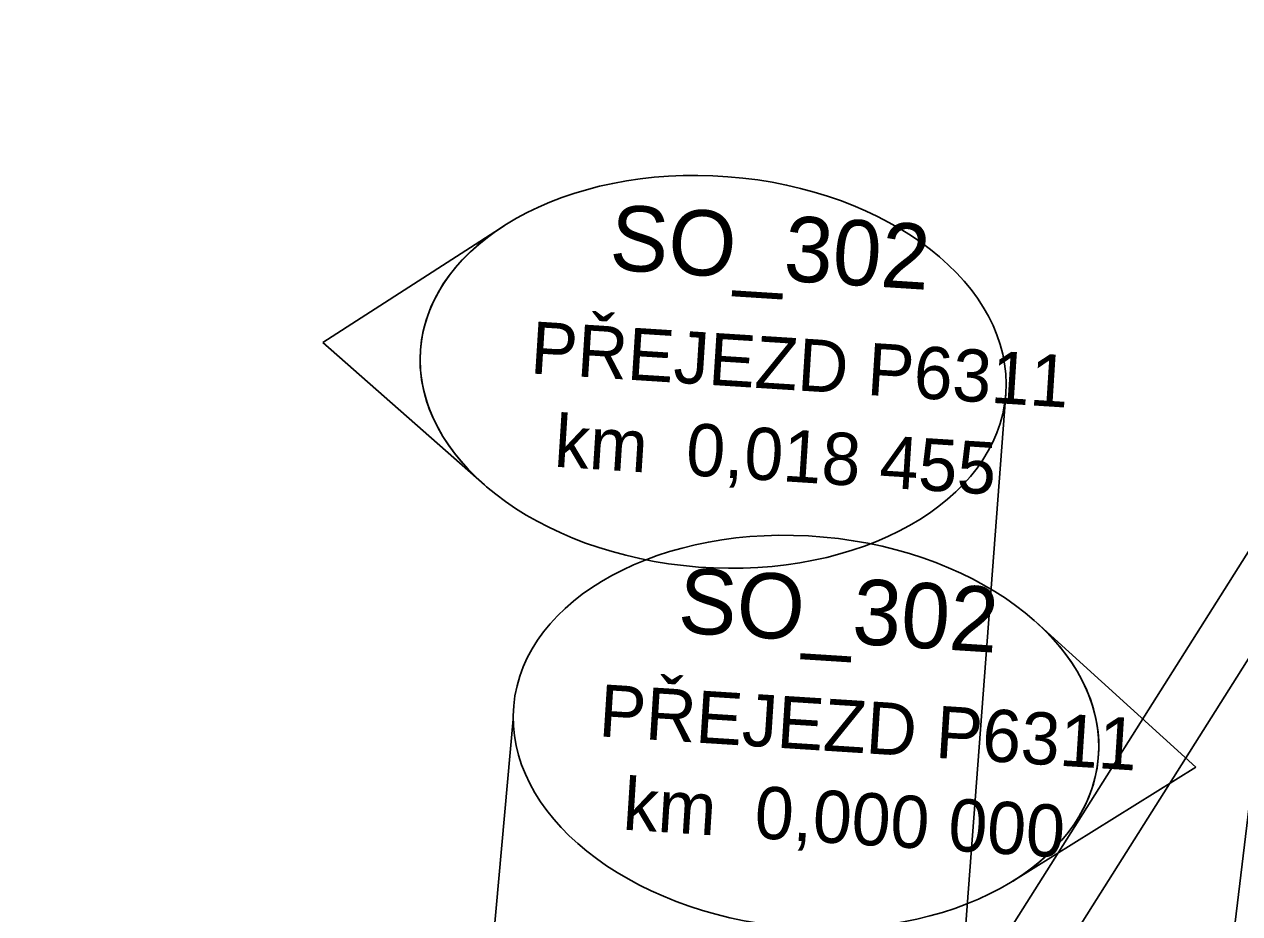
# Model space of a CAD drawing. Extents: x -743359 to -742769, y -1127804 to -1126284.
# Drawn here: x -743198.3 to -743151.71, y -1127071.55 to -1127037.47 of the extents above; entities that cross this region are included whole.
import ezdxf

# ---------------------------------------------------------------- set-up
doc = ezdxf.new("R2010")
doc.units = 0
for name, color, linetype in [('_Násyp', 7, 'Continuous'), ('_Zabezpečovací zařízení_trasa', 7, 'Continuous'), ('bublina_fialová_čára_tenká', 7, 'Continuous'), ('bublina_růžová_230_čára_tučná', 7, 'Continuous'), ('SMER_VYS_VYROVNANI', 7, 'Continuous')]:
    doc.layers.add(name, color=color, linetype=linetype)

msp = doc.modelspace()

# ---------------------------------------------------------------- linework, layer by layer
at = {"layer": '_Zabezpečovací zařízení_trasa'}
msp.add_lwpolyline([(-743098.647, -1126974.146), (-743125.94, -1127017.384), (-743152.604, -1127059.608), (-743175.023, -1127095.116), (-743199.163, -1127133.346), (-743215.971, -1127159.941), (-743232.818, -1127186.515), (-743247.456, -1127209.811), (-743254.52, -1127221.639), (-743261.299, -1127233.691), (-743264.155, -1127239.195), (-743264.862, -1127241.108), (-743267.337, -1127245.816), (-743268.289, -1127247.159), (-743271.711, -1127253.75), (-743281.122, -1127274.196), (-743291.923, -1127301.42), (-743296.724, -1127315.222), (-743301.116, -1127329.128), (-743306.787, -1127349.506), (-743311.536, -1127370.056), (-743315.693, -1127392.87), (-743318.79, -1127415.837)], dxfattribs=at)
at = {"layer": 'bublina_fialová_čára_tenká'}
for p, q in [((-743145.088, -1127015.481), (-743152.928, -1127080.479)), ((-743160.679, -1127051.634), (-743164.286, -1127099.423)), ((-743179.562, -1127064.096), (-743182.5, -1127096.45))]:
    msp.add_line(p, q, dxfattribs=at)
at = {"layer": 'bublina_růžová_230_čára_tučná'}
for p, q in [((-743179.913, -1127045.19), (-743186.854, -1127049.658)), ((-743179.913, -1127045.19), (-743186.854, -1127049.658)), ((-743186.854, -1127049.658), (-743180.663, -1127055.117)), ((-743186.854, -1127049.658), (-743180.663, -1127055.117)), ((-743159.51, -1127060.384), (-743153.397, -1127065.932)), ((-743159.51, -1127060.384), (-743153.397, -1127065.932)), ((-743153.397, -1127065.932), (-743160.402, -1127070.299)), ((-743153.397, -1127065.932), (-743160.402, -1127070.299))]:
    msp.add_line(p, q, dxfattribs=at)
for centre, major_axis in [((-743171.897, -1127050.787), (11.218, -0.847)), ((-743168.337, -1127064.588), (-11.205, 1.008))]:
    msp.add_ellipse(centre, major_axis=major_axis, ratio=0.666667, dxfattribs=at)
for centre, major_axis in [((-743171.897, -1127050.787), (-11.22, 0.847)), ((-743168.337, -1127064.588), (11.206, -1.008))]:
    msp.add_ellipse(centre, major_axis=major_axis, ratio=0.666473, start_param=5.557317, end_param=7.009053, dxfattribs=at)
at = {"layer": 'SMER_VYS_VYROVNANI'}
msp.add_lwpolyline([(-743143.427, -1127049.192), (-743169.53, -1127090.542)], dxfattribs=at)

# ---------------------------------------------------------------- texts
at = {"layer": '_Násyp'}
for s, height, p in [('SO_302', 2.5, (-743175.908, -1127046.867)), ('PŘEJEZD P6311', 2, (-743178.937, -1127050.846)), ('km  0,018 455', 2, (-743178.022, -1127054.419)), ('SO_302', 2.5, (-743173.286, -1127060.774)), ('PŘEJEZD P6311', 2, (-743176.314, -1127064.752)), ('km  0,000 000', 2, (-743175.393, -1127068.327))]:
    msp.add_text(s, height=height, rotation=356.3528, dxfattribs=at).set_placement(p)

doc.saveas('drawing.dxf')
